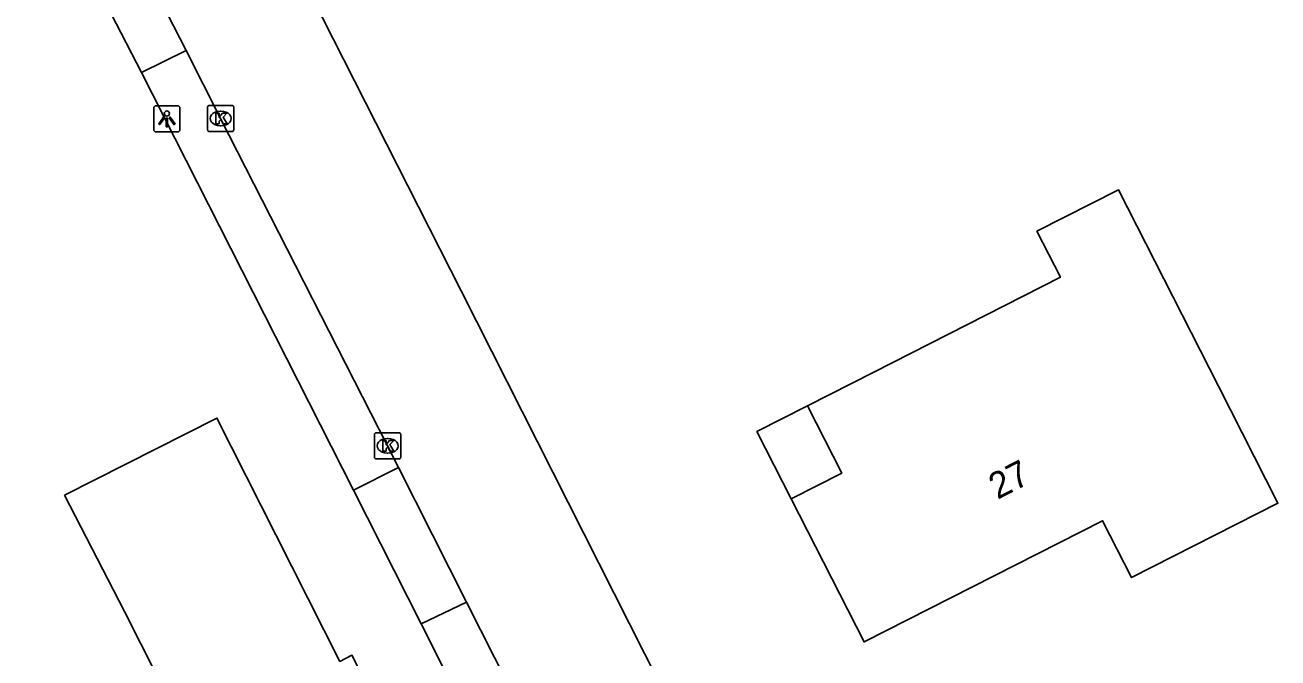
# Model space of a CAD drawing. Extents: x 162722 to 165099, y 384721 to 386283.
# Drawn here: x 164013.51 to 164061.23, y 385015.28 to 385039.4 of the extents above; entities that cross this region are included whole.
import ezdxf

# ---------------------------------------------------------------- set-up
doc = ezdxf.new("R2010")
doc.units = 0
for name, color, linetype in [('IMGEO_Kolk', 7, 'Continuous'), ('IMGEO_Lichtpunt', 7, 'Continuous'), ('IMGEO_Pand', 7, 'Continuous'), ('IMGEO_Pand_nummerreeks', 7, 'Continuous'), ('IMGEO_Pand_overbouw', 7, 'Continuous'), ('IMGEO_Parkeervlak_open', 7, 'Continuous'), ('IMGEO_Rijbaan_lokaal_open', 7, 'Continuous'), ('IMGEO_Voetpad_open', 7, 'Continuous')]:
    doc.layers.add(name, color=color, linetype=linetype)

msp = doc.modelspace()

# ---------------------------------------------------------------- linework, layer by layer
at = {"layer": 'IMGEO_Kolk'}
for p, q in [((164020.461, 385035.41), (164020.461, 385036.262)), ((164020.536, 385036.336), (164021.388, 385036.336)), ((164020.949, 385036.116), (164020.974, 385036.116)), ((164021.462, 385036.262), (164021.462, 385035.41)), ((164021.388, 385035.336), (164020.536, 385035.336)), ((164020.972, 385035.556), (164020.947, 385035.556)), ((164026.819, 385022.937), (164026.819, 385023.789)), ((164026.894, 385023.863), (164027.746, 385023.863)), ((164027.82, 385023.789), (164027.82, 385022.937)), ((164027.307, 385023.643), (164027.332, 385023.643)), ((164027.746, 385022.863), (164026.894, 385022.863)), ((164027.33, 385023.083), (164027.305, 385023.083))]:
    msp.add_line(p, q, dxfattribs=at)
for points in [[(164020.461, 385035.41), (164020.461, 385036.262)], [(164020.536, 385036.336), (164021.388, 385036.336)], [(164021.462, 385036.262), (164021.462, 385035.41)], [(164020.782, 385036.036), (164020.905, 385036.036), (164020.905, 385035.885), (164021.035, 385036.036), (164021.199, 385036.036), (164021.053, 385035.885), (164021.206, 385035.636), (164021.054, 385035.636), (164020.969, 385035.8), (164020.905, 385035.733), (164020.905, 385035.636), (164020.782, 385035.636), (164020.782, 385036.036)], [(164021.388, 385035.336), (164020.536, 385035.336)], [(164026.819, 385022.937), (164026.819, 385023.789)], [(164026.894, 385023.863), (164027.746, 385023.863)], [(164027.82, 385023.789), (164027.82, 385022.937)], [(164027.14, 385023.563), (164027.263, 385023.563), (164027.263, 385023.412), (164027.393, 385023.563), (164027.557, 385023.563), (164027.411, 385023.412), (164027.564, 385023.163), (164027.412, 385023.163), (164027.327, 385023.327), (164027.263, 385023.26), (164027.263, 385023.163), (164027.14, 385023.163), (164027.14, 385023.563)], [(164027.746, 385022.863), (164026.894, 385022.863)]]:
    msp.add_lwpolyline(points, dxfattribs=at)
for centre, start, end in [((164020.538, 385036.26), 91.552, 178.448), ((164020.538, 385036.26), 91.552, 178.448), ((164021.386, 385036.26), 1.552, 88.448), ((164021.386, 385036.26), 1.552, 88.448), ((164020.538, 385035.412), 181.552, 268.448), ((164020.538, 385035.412), 181.552, 268.448), ((164021.386, 385035.412), 271.552, 358.448), ((164021.386, 385035.412), 271.552, 358.448), ((164026.896, 385023.787), 91.552, 178.448), ((164026.896, 385023.787), 91.552, 178.448), ((164027.744, 385023.787), 1.552, 88.448), ((164027.744, 385023.787), 1.552, 88.448), ((164026.896, 385022.939), 181.552, 268.448), ((164026.896, 385022.939), 181.552, 268.448), ((164027.744, 385022.939), 271.552, 358.448), ((164027.744, 385022.939), 271.552, 358.448)]:
    msp.add_arc(centre, 0.0765, start, end, dxfattribs=at)
for centre, major_axis, ratio, start_param, end_param in [((164020.948, 385035.836), (-0.387, 0.002), 0.722429, 4.712389, 7.853982), ((164020.973, 385035.836), (-0.39, 0.002), 0.717154, 1.570796, 4.712389), ((164027.306, 385023.363), (-0.387, 0.002), 0.722429, 4.712389, 7.853982), ((164027.331, 385023.363), (-0.39, 0.002), 0.717154, 1.570796, 4.712389)]:
    msp.add_ellipse(centre, major_axis=major_axis, ratio=ratio, start_param=start_param, end_param=end_param, dxfattribs=at)
at = {"layer": 'IMGEO_Lichtpunt'}
for p, q in [((164018.416, 385036.227), (164018.416, 385035.42)), ((164018.416, 385036.227), (164018.416, 385035.42)), ((164019.318, 385036.322), (164018.51, 385036.322)), ((164019.318, 385036.322), (164018.51, 385036.322)), ((164019.412, 385035.42), (164019.412, 385036.227)), ((164019.412, 385035.42), (164019.412, 385036.227)), ((164018.51, 385035.326), (164019.318, 385035.326)), ((164018.51, 385035.326), (164019.318, 385035.326))]:
    msp.add_line(p, q, dxfattribs=at)
for points in [[(164018.79, 385035.891), (164018.829, 385035.863), (164018.641, 385035.601), (164018.603, 385035.628), (164018.79, 385035.891)], [(164018.892, 385035.843), (164018.939, 385035.843), (164018.939, 385035.521), (164018.892, 385035.521), (164018.892, 385035.843)], [(164019.002, 385035.863), (164019.04, 385035.89), (164019.227, 385035.628), (164019.188, 385035.6), (164019.002, 385035.863)]]:
    msp.add_lwpolyline(points, dxfattribs=at)
msp.add_circle((164018.915, 385036.025), 0.0994, dxfattribs=at)
for centre, start, end in [((164018.51, 385036.227), 90, 180), ((164018.51, 385036.227), 90, 180), ((164019.318, 385036.227), 0, 90), ((164019.318, 385036.227), 0, 90), ((164018.51, 385035.42), 180, 270), ((164018.51, 385035.42), 180, 270), ((164019.318, 385035.42), 270, 0), ((164019.318, 385035.42), 270, 360)]:
    msp.add_arc(centre, 0.0946, start, end, dxfattribs=at)
at = {"layer": 'IMGEO_Pand'}
for points in [[(164058.963, 385025.633), (164055.156, 385033.119), (164052.051, 385031.539), (164052.943, 385029.785), (164045.845, 385026.174), (164043.314, 385024.887), (164044.615, 385022.327), (164042.691, 385021.345), (164045.465, 385015.89), (164054.551, 385020.511), (164055.655, 385018.34), (164061.23, 385021.176), (164058.963, 385025.633)], [(164015.017, 385021.483), (164020.817, 385024.418), (164023.07, 385019.965), (164025.507, 385015.149), (164025.963, 385015.38), (164029.686, 385008.024), (164022.613, 385004.445), (164023.648, 385002.4), (164018.982, 385000), (164018.286, 384999.642), (164018.104, 385000), (164016.015, 385004.097), (164013.513, 385009.006), (164019.769, 385012.173), (164017.302, 385017.046), (164015.017, 385021.483)]]:
    msp.add_lwpolyline(points, dxfattribs=at)
at = {"layer": 'IMGEO_Pand_overbouw'}
msp.add_lwpolyline([(164043.314, 385024.887), (164041.388, 385023.907), (164042.691, 385021.345), (164044.615, 385022.327)], close=True, dxfattribs=at)
at = {"layer": 'IMGEO_Parkeervlak_open'}
msp.add_lwpolyline([(164034.695, 385004.457), (164028.601, 385016.574)], dxfattribs=at)
at = {"layer": 'IMGEO_Rijbaan_lokaal_open'}
for points in [[(164040.957, 385008.624), (164040.599, 385008.534), (164030.122, 385029.274), (164017.119, 385054.888)], [(164017.722, 385042.203), (164019.645, 385038.43)], [(164019.645, 385038.43), (164020.962, 385035.836), (164027.32, 385023.363), (164027.737, 385022.536)], [(164027.737, 385022.536), (164030.324, 385017.406)], [(164036.222, 385005.682), (164035.109, 385007.943), (164030.324, 385017.406)]]:
    msp.add_lwpolyline(points, dxfattribs=at)
at = {"layer": 'IMGEO_Voetpad_open'}
for points in [[(164017.949, 385037.586), (164016.024, 385041.339)], [(164019.645, 385038.43), (164017.949, 385037.586)], [(164026.02, 385021.678), (164017.949, 385037.586)], [(164027.737, 385022.536), (164026.02, 385021.678)], [(164028.601, 385016.574), (164026.02, 385021.678)], [(164030.324, 385017.406), (164028.601, 385016.574)]]:
    msp.add_lwpolyline(points, dxfattribs=at)

# ---------------------------------------------------------------- texts
at = {"layer": 'IMGEO_Pand_nummerreeks'}
msp.add_text('27', height=1, rotation=26.9577, dxfattribs=at).set_placement((164050.546, 385021.302))

doc.saveas('drawing.dxf')
